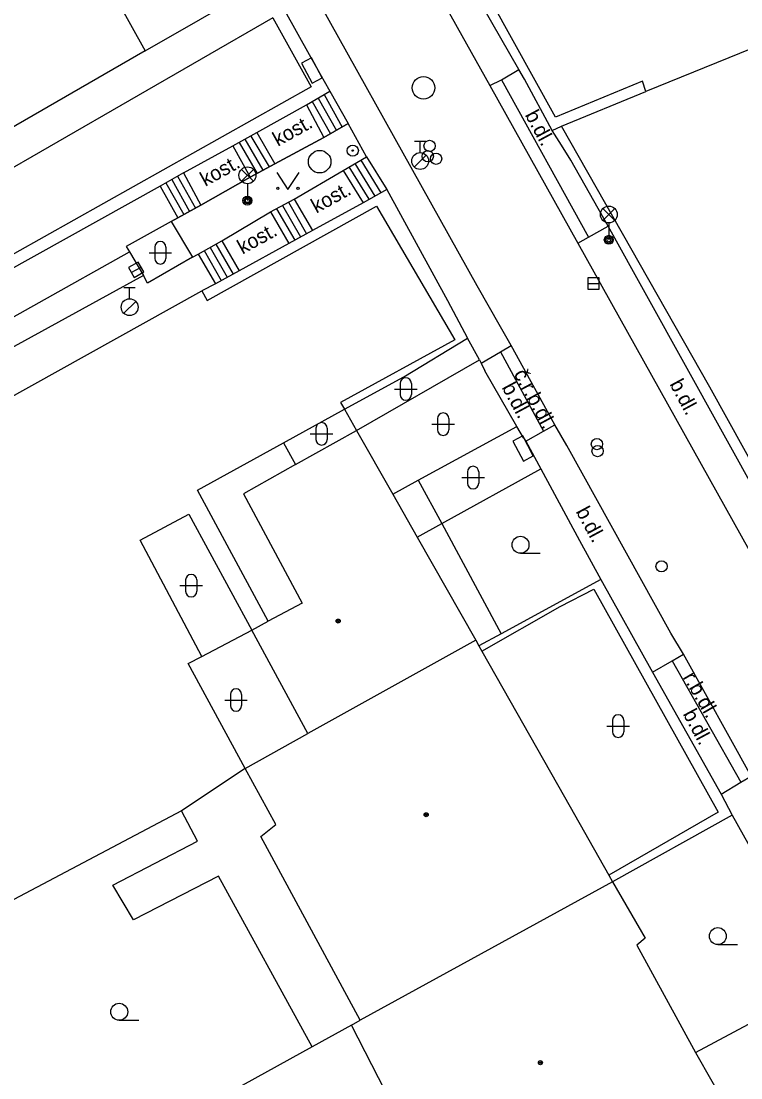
# Model space of a CAD drawing. Extents: x -600391 to -599491, y -1160176 to -1159402.
# Drawn here: x -600336.91 to -600304.95, y -1159781.21 to -1159734.28 of the extents above; entities that cross this region are included whole.
import ezdxf

# ---------------------------------------------------------------- set-up
doc = ezdxf.new("R2010")
doc.units = 0
for name, color, linetype in [('Level 10', 7, 'Continuous'), ('Level 11', 7, 'Continuous'), ('Level 24', 7, 'Continuous'), ('Level 25', 7, 'Continuous'), ('Level 27', 7, 'Continuous'), ('Level 28', 7, 'Continuous'), ('Level 33', 7, 'Continuous'), ('Level 36', 7, 'Continuous'), ('Level 39', 7, 'Continuous'), ('Level 40', 7, 'Continuous'), ('Level 5', 7, 'Continuous'), ('Level 51', 7, 'Continuous'), ('Level 7', 7, 'Continuous'), ('Level 8', 7, 'Continuous'), ('Level 9', 7, 'Continuous')]:
    doc.layers.add(name, color=color, linetype=linetype)

msp = doc.modelspace()

# ---------------------------------------------------------------- linework, layer by layer
at = {"layer": 'Level 10'}
for points in [[(-600328.52, -1159714.89), (-600328.3, -1159715.33), (-600321.84, -1159726.86), (-600316.09, -1159737.14)], [(-600315.15, -1159748.68), (-600315.62, -1159747.86), (-600316.66, -1159746.03), (-600326.09, -1159729.11), (-600327.4, -1159726.83)], [(-600316.09, -1159737.14), (-600312.19, -1159744.14)], [(-600312.19, -1159744.14), (-600302.73, -1159761.08)], [(-600313.21, -1159752.2), (-600315.15, -1159748.68)], [(-600307.5, -1159762.39), (-600308.05, -1159761.45), (-600312.68, -1159753.12), (-600313.21, -1159752.2)], [(-600304.49, -1159767.81), (-600307.5, -1159762.39)]]:
    msp.add_lwpolyline(points, dxfattribs=at)
at = {"layer": 'Level 11'}
for points in [[(-600331.4, -1159735.6), (-600326.48, -1159732.77)], [(-600325.73, -1159734.13), (-600338.47, -1159741.47)], [(-600315.57, -1159736.88), (-600314.81, -1159736.42)], [(-600316.09, -1159737.14), (-600315.57, -1159736.88)], [(-600315.57, -1159736.88), (-600311.71, -1159743.87)], [(-600323.2, -1159737.39), (-600322.39, -1159738.83)], [(-600323.98, -1159737.85), (-600323.17, -1159739.28)], [(-600323.72, -1159737.7), (-600322.91, -1159739.13)], [(-600323.45, -1159737.54), (-600322.65, -1159738.98)], [(-600324.24, -1159738), (-600323.47, -1159739.45)], [(-600322.39, -1159738.83), (-600323.47, -1159739.45)], [(-600321.57, -1159740.3), (-600322.39, -1159738.83)], [(-600326.7, -1159739.38), (-600325.9, -1159740.75)], [(-600326.44, -1159739.23), (-600325.64, -1159740.61)], [(-600327.51, -1159739.82), (-600326.74, -1159741.21)], [(-600327.23, -1159739.67), (-600326.43, -1159741.04)], [(-600326.97, -1159739.52), (-600326.17, -1159740.9)], [(-600323.47, -1159739.45), (-600325.64, -1159740.61)], [(-600322.61, -1159740.91), (-600321.57, -1159740.3)], [(-600321.57, -1159740.3), (-600320.67, -1159741.76)], [(-600325.64, -1159740.61), (-600326.74, -1159741.21)], [(-600322.35, -1159740.75), (-600321.46, -1159742.19)], [(-600322.09, -1159740.6), (-600321.2, -1159742.05)], [(-600321.83, -1159740.45), (-600320.93, -1159741.9)], [(-600329.96, -1159741.16), (-600329.17, -1159742.58)], [(-600329.7, -1159741.02), (-600328.93, -1159742.45)], [(-600326.74, -1159741.21), (-600328.93, -1159742.45)], [(-600324.78, -1159742.18), (-600322.61, -1159740.91)], [(-600322.61, -1159740.91), (-600321.72, -1159742.34)], [(-600330.74, -1159741.6), (-600329.95, -1159743.02)], [(-600330.48, -1159741.46), (-600329.69, -1159742.87)], [(-600330.22, -1159741.31), (-600329.43, -1159742.73)], [(-600325.84, -1159742.75), (-600324.78, -1159742.18)], [(-600324.78, -1159742.18), (-600323.97, -1159743.57)], [(-600328.93, -1159742.45), (-600329.95, -1159743.02)], [(-600325.57, -1159742.61), (-600324.76, -1159744)], [(-600325.3, -1159742.47), (-600324.5, -1159743.86)], [(-600325.04, -1159742.32), (-600324.24, -1159743.72)], [(-600329.95, -1159743.02), (-600330.24, -1159743.18)], [(-600327.99, -1159744.04), (-600325.84, -1159742.75)], [(-600325.84, -1159742.75), (-600325.02, -1159744.15)], [(-600330.24, -1159743.18), (-600332.24, -1159744.29), (-600332.1, -1159744.52)], [(-600330.24, -1159743.18), (-600329.3, -1159744.76)], [(-600311.71, -1159743.87), (-600310.84, -1159743.39)], [(-600329.05, -1159744.62), (-600327.99, -1159744.04)], [(-600327.99, -1159744.04), (-600327.23, -1159745.36)], [(-600312.19, -1159744.14), (-600311.71, -1159743.87)], [(-600352.17, -1159755.78), (-600332.1, -1159744.52)], [(-600332.1, -1159744.52), (-600331.48, -1159745.58)], [(-600328.78, -1159744.47), (-600328.02, -1159745.8)], [(-600328.52, -1159744.33), (-600327.76, -1159745.65)], [(-600328.26, -1159744.19), (-600327.49, -1159745.51)], [(-600329.3, -1159744.76), (-600331.29, -1159745.91), (-600331.48, -1159745.58)], [(-600329.3, -1159744.76), (-600329.05, -1159744.62)], [(-600329.05, -1159744.62), (-600328.28, -1159745.94)], [(-600331.48, -1159745.58), (-600340.25, -1159750.38)], [(-600315.62, -1159748.97), (-600315.15, -1159748.68)], [(-600316.48, -1159749.46), (-600315.62, -1159748.97)], [(-600315.62, -1159748.97), (-600313.71, -1159752.48)], [(-600322.02, -1159752.45), (-600316.56, -1159749.32)], [(-600325.25, -1159753), (-600322.55, -1159751.51)], [(-600322.55, -1159751.51), (-600322.02, -1159752.45)], [(-600319.27, -1159754.67), (-600314.89, -1159752.28)], [(-600314.5, -1159752.93), (-600313.71, -1159752.48)], [(-600313.71, -1159752.48), (-600313.21, -1159752.2)], [(-600324.72, -1159753.97), (-600327.04, -1159755.27), (-600324.43, -1159760.13), (-600325.94, -1159760.93)], [(-600318.23, -1159756.59), (-600313.83, -1159754.16)], [(-600320.4, -1159755.29), (-600319.27, -1159754.67)], [(-600319.27, -1159754.67), (-600318.23, -1159756.59)], [(-600328.89, -1159762.5), (-600331.62, -1159757.33), (-600329.46, -1159756.17), (-600326.67, -1159761.32)], [(-600319.32, -1159757.19), (-600318.23, -1159756.59)], [(-600318.23, -1159756.59), (-600315.59, -1159761.48)], [(-600328.89, -1159762.5), (-600326.67, -1159761.32)], [(-600326.96, -1159767.46), (-600329.49, -1159762.81), (-600328.89, -1159762.5)], [(-600308.87, -1159763.19), (-600307.99, -1159762.68)], [(-600307.99, -1159762.68), (-600307.5, -1159762.39)], [(-600307.99, -1159762.68), (-600304.95, -1159768.08)], [(-600304.95, -1159768.08), (-600304.49, -1159767.81)], [(-600305.82, -1159768.6), (-600304.95, -1159768.08)], [(-600306.96, -1159780.08), (-600301.17, -1159776.98)]]:
    msp.add_lwpolyline(points, dxfattribs=at)
at = {"layer": 'Level 24'}
for points in [[(-600324.456, -1159736.147), (-600323.985, -1159737.029), (-600323.544, -1159736.793), (-600324.015, -1159735.911)], [(-600315.076, -1159752.936), (-600314.606, -1159753.819), (-600314.164, -1159753.584), (-600314.634, -1159752.701)]]:
    msp.add_lwpolyline(points, close=True, dxfattribs=at)
at = {"layer": 'Level 25'}
for radius in [0.25, 0.0303]:
    msp.add_circle((-600322.18, -1159740.03), radius, dxfattribs=at)
at = {"layer": 'Level 27'}
for p, q in [((-600332.018, -1159745.443), (-600331.582, -1159745.197)), ((-600311.74, -1159745.93), (-600311.24, -1159745.93))]:
    msp.add_line(p, q, dxfattribs=at)
for points in [[(-600331.895, -1159745.66), (-600331.46, -1159745.415), (-600331.705, -1159744.98), (-600332.14, -1159745.225)], [(-600311.74, -1159746.18), (-600311.24, -1159746.18), (-600311.24, -1159745.68), (-600311.74, -1159745.68)]]:
    msp.add_lwpolyline(points, close=True, dxfattribs=at)
for centre in [(-600319.04, -1159737.24), (-600323.65, -1159740.52)]:
    msp.add_circle(centre, 0.5, dxfattribs=at)
at = {"layer": 'Level 28'}
for p, q in [((-600319.44, -1159739.615), (-600318.94, -1159739.615)), ((-600319.19, -1159740.115), (-600319.19, -1159739.615)), ((-600319.448, -1159740.762), (-600318.918, -1159740.232)), ((-600332.34, -1159746.105), (-600331.84, -1159746.105)), ((-600332.09, -1159746.605), (-600332.09, -1159746.105)), ((-600332.348, -1159747.252), (-600331.818, -1159746.722))]:
    msp.add_line(p, q, dxfattribs=at)
for centre, radius in [((-600318.77, -1159739.82), 0.25), ((-600319.19, -1159740.49), 0.375), ((-600318.85, -1159740.28), 0.25), ((-600318.48, -1159740.39), 0.25), ((-600332.09, -1159746.98), 0.375), ((-600311.34, -1159753.06), 0.25), ((-600311.31, -1159753.37), 0.25), ((-600308.47, -1159758.49), 0.25)]:
    msp.add_circle(centre, radius, dxfattribs=at)
at = {"layer": 'Level 33'}
for p, q in [((-600327.125, -1159741.39), (-600326.595, -1159740.86)), ((-600327.125, -1159740.86), (-600326.595, -1159741.39)), ((-600326.86, -1159741.5), (-600326.86, -1159742.25)), ((-600311.075, -1159743.13), (-600310.545, -1159742.6)), ((-600311.075, -1159742.6), (-600310.545, -1159743.13)), ((-600310.81, -1159743.24), (-600310.81, -1159743.99))]:
    msp.add_line(p, q, dxfattribs=at)
for centre, radius in [((-600326.86, -1159741.125), 0.375), ((-600326.86, -1159742.25), 0.2), ((-600326.86, -1159742.25), 0.145), ((-600326.86, -1159742.25), 0.0876), ((-600310.81, -1159742.865), 0.375), ((-600310.81, -1159743.99), 0.2), ((-600310.81, -1159743.99), 0.145), ((-600310.81, -1159743.99), 0.0876)]:
    msp.add_circle(centre, radius, dxfattribs=at)
at = {"layer": 'Level 36'}
for p, q in [((-600330.976, -1159744.316), (-600330.976, -1159744.816)), ((-600330.476, -1159744.316), (-600330.476, -1159744.816)), ((-600331.226, -1159744.566), (-600330.226, -1159744.566)), ((-600320.326, -1159750.616), (-600319.326, -1159750.616)), ((-600320.076, -1159750.366), (-600320.076, -1159750.866)), ((-600319.576, -1159750.366), (-600319.576, -1159750.866)), ((-600318.416, -1159751.926), (-600318.416, -1159752.426)), ((-600317.916, -1159751.926), (-600317.916, -1159752.426)), ((-600323.816, -1159752.356), (-600323.816, -1159752.856)), ((-600323.316, -1159752.356), (-600323.316, -1159752.856)), ((-600318.666, -1159752.176), (-600317.666, -1159752.176)), ((-600324.066, -1159752.606), (-600323.066, -1159752.606)), ((-600317.086, -1159754.296), (-600317.086, -1159754.796)), ((-600316.586, -1159754.296), (-600316.586, -1159754.796)), ((-600317.336, -1159754.546), (-600316.336, -1159754.546)), ((-600314.73, -1159757.905), (-600313.855, -1159757.905)), ((-600329.606, -1159759.096), (-600329.606, -1159759.596)), ((-600329.106, -1159759.096), (-600329.106, -1159759.596)), ((-600329.856, -1159759.346), (-600328.856, -1159759.346)), ((-600327.616, -1159764.176), (-600327.616, -1159764.676)), ((-600327.116, -1159764.176), (-600327.116, -1159764.676)), ((-600327.866, -1159764.426), (-600326.866, -1159764.426)), ((-600310.896, -1159765.586), (-600309.896, -1159765.586)), ((-600310.646, -1159765.336), (-600310.646, -1159765.836)), ((-600310.146, -1159765.336), (-600310.146, -1159765.836)), ((-600305.97, -1159775.285), (-600305.095, -1159775.285)), ((-600332.55, -1159778.645), (-600331.675, -1159778.645))]:
    msp.add_line(p, q, dxfattribs=at)
msp.add_lwpolyline([(-600325.56, -1159741), (-600325.06, -1159741.75), (-600324.56, -1159741)], dxfattribs=at)
for centre, radius in [((-600325.51, -1159741.7), 0.05), ((-600324.611, -1159741.7), 0.05), ((-600314.73, -1159757.53), 0.375), ((-600305.97, -1159774.91), 0.375), ((-600332.55, -1159778.27), 0.375)]:
    msp.add_circle(centre, radius, dxfattribs=at)
for centre, start, end in [((-600330.726, -1159744.316), 0, 180), ((-600330.726, -1159744.816), 180, 0), ((-600319.826, -1159750.366), 0, 180), ((-600319.826, -1159750.866), 180, 0), ((-600318.166, -1159751.926), 0, 180), ((-600323.566, -1159752.356), 0, 180), ((-600318.166, -1159752.426), 180, 0), ((-600323.566, -1159752.856), 180, 0), ((-600316.836, -1159754.296), 0, 180), ((-600316.836, -1159754.796), 180, 0), ((-600329.356, -1159759.096), 0, 180), ((-600329.356, -1159759.596), 180, 0), ((-600327.366, -1159764.176), 0, 180), ((-600327.366, -1159764.676), 180, 0), ((-600310.396, -1159765.336), 0, 180), ((-600310.396, -1159765.836), 180, 0)]:
    msp.add_arc(centre, 0.25, start, end, dxfattribs=at)
at = {"layer": 'Level 39'}
for centre, radius in [((-600322.83, -1159760.92), 0.09), ((-600322.83, -1159760.92), 0.0398), ((-600318.92, -1159769.52), 0.09), ((-600318.92, -1159769.52), 0.0398), ((-600313.85, -1159780.53), 0.09), ((-600313.85, -1159780.53), 0.0398)]:
    msp.add_circle(centre, radius, dxfattribs=at)
at = {"layer": 'Level 5'}
for points in [[(-600336.24, -1159726.9), (-600331.4, -1159735.6)], [(-600331.4, -1159735.6), (-600339.26, -1159740.12)], [(-600324.72, -1159753.97), (-600322.02, -1159752.45)], [(-600322.02, -1159752.45), (-600320.4, -1159755.29)], [(-600329.08, -1159755.1), (-600325.25, -1159753)], [(-600325.25, -1159753), (-600324.72, -1159753.97)], [(-600325.94, -1159760.93), (-600329.08, -1159755.1)], [(-600320.4, -1159755.29), (-600319.32, -1159757.19)], [(-600319.32, -1159757.19), (-600316.72, -1159761.77)], [(-600326.67, -1159761.32), (-600325.94, -1159760.93)], [(-600324.18, -1159765.92), (-600326.67, -1159761.32)], [(-600316.72, -1159761.77), (-600324.18, -1159765.92)], [(-600316.72, -1159761.77), (-600316.58, -1159762.02)], [(-600316.58, -1159762.02), (-600316.45, -1159762.26)], [(-600316.45, -1159762.26), (-600312.78, -1159768.72)], [(-600326.96, -1159767.46), (-600324.18, -1159765.92)], [(-600325.6, -1159769.96), (-600326.96, -1159767.46)], [(-600312.78, -1159768.72), (-600310.81, -1159772.2)], [(-600326.26, -1159770.49), (-600325.6, -1159769.96)], [(-600321.85, -1159778.65), (-600326.26, -1159770.49)], [(-600310.81, -1159772.2), (-600310.64, -1159772.5)], [(-600310.64, -1159772.5), (-600321.85, -1159778.65)], [(-600310.64, -1159772.5), (-600309.2, -1159775)], [(-600309.2, -1159775), (-600309.56, -1159775.31)], [(-600309.56, -1159775.31), (-600306.96, -1159780.08)], [(-600322.24, -1159778.87), (-600321.85, -1159778.65)], [(-600320.14, -1159782.97), (-600322.24, -1159778.87)], [(-600306.96, -1159780.08), (-600305.51, -1159782.63)]]:
    msp.add_lwpolyline(points, dxfattribs=at)
at = {"layer": 'Level 51'}
for points in [[(-600326.96, -1159767.46), (-600329.78, -1159769.35)], [(-600329.78, -1159769.35), (-600341.11, -1159775.33)], [(-600329.08, -1159770.69), (-600329.78, -1159769.35)], [(-600332.83, -1159772.65), (-600329.08, -1159770.69)], [(-600331.92, -1159774.18), (-600332.83, -1159772.65)], [(-600328.15, -1159772.25), (-600331.92, -1159774.18)], [(-600323.99, -1159779.83), (-600328.15, -1159772.25)], [(-600322.24, -1159778.87), (-600323.99, -1159779.83)], [(-600323.99, -1159779.83), (-600335.29, -1159786.07)]]:
    msp.add_lwpolyline(points, dxfattribs=at)
at = {"layer": 'Level 7'}
for points in [[(-600285.09, -1159727.62), (-600309.17, -1159737.41)], [(-600309.31, -1159736.95), (-600313.18, -1159738.55), (-600316.94, -1159731.75), (-600313.05, -1159729.5)], [(-600314.81, -1159736.42), (-600317.61, -1159731.54)], [(-600325.73, -1159734.13), (-600324.03, -1159737.2), (-600353.03, -1159753.48), (-600355.24, -1159749.56), (-600360.24, -1159740.73)], [(-600325.2, -1159733.82), (-600324.12, -1159735.76), (-600323.45, -1159736.94), (-600323.2, -1159737.39)], [(-600313.32, -1159739.14), (-600314.55, -1159736.85), (-600314.81, -1159736.42)], [(-600309.17, -1159737.41), (-600309.31, -1159736.95)], [(-600324.24, -1159738), (-600323.2, -1159737.39)], [(-600312.91, -1159738.94), (-600309.17, -1159737.41)], [(-600326.44, -1159739.23), (-600324.24, -1159738)], [(-600327.51, -1159739.82), (-600326.44, -1159739.23)], [(-600313.32, -1159739.14), (-600312.91, -1159738.94)], [(-600310.84, -1159743.39), (-600312.5, -1159740.46), (-600312.91, -1159739.78), (-600313.32, -1159739.14)], [(-600295.86, -1159757.73), (-600296.01, -1159757.35), (-600300.97, -1159760.2), (-600306.33, -1159750.54), (-600312.91, -1159738.94)], [(-600329.7, -1159741.02), (-600327.51, -1159739.82)], [(-600329.7, -1159741.02), (-600330.74, -1159741.6)], [(-600330.74, -1159741.6), (-600353.06, -1159754.02)], [(-600320.67, -1159741.76), (-600321.72, -1159742.34)], [(-600320.67, -1159741.76), (-600317.97, -1159746.68), (-600317.09, -1159748.35)], [(-600328.64, -1159746.68), (-600321.12, -1159742.5), (-600317.65, -1159748.43), (-600322.72, -1159751.21)], [(-600321.72, -1159742.34), (-600323.97, -1159743.57)], [(-600323.97, -1159743.57), (-600325.02, -1159744.15)], [(-600301.34, -1159760.31), (-600303.58, -1159756.43), (-600304.05, -1159755.63), (-600310.84, -1159743.39)], [(-600325.02, -1159744.15), (-600327.23, -1159745.36)], [(-600327.23, -1159745.36), (-600328.28, -1159745.94)], [(-600328.28, -1159745.94), (-600328.89, -1159746.26)], [(-600350.38, -1159758.22), (-600328.89, -1159746.26)], [(-600328.89, -1159746.26), (-600328.64, -1159746.68)], [(-600322.55, -1159751.51), (-600319.92, -1159750.07), (-600317.09, -1159748.35)], [(-600316.56, -1159749.32), (-600316.48, -1159749.46)], [(-600316.48, -1159749.46), (-600316.32, -1159749.81)], [(-600322.72, -1159751.21), (-600322.55, -1159751.51)], [(-600314.6, -1159752.79), (-600314.5, -1159752.93)], [(-600314.5, -1159752.93), (-600313.83, -1159754.16)], [(-600313.83, -1159754.16), (-600312.11, -1159757.34), (-600311.17, -1159759.07)], [(-600311.17, -1159759.07), (-600315.59, -1159761.48)], [(-600311.17, -1159759.07), (-600308.87, -1159763.19)], [(-600316.45, -1159762.26), (-600312.97, -1159760.28), (-600311.48, -1159759.51), (-600305.96, -1159769.41), (-600310.81, -1159772.2)], [(-600315.59, -1159761.48), (-600316.58, -1159762.02)], [(-600308.87, -1159763.19), (-600305.82, -1159768.6)], [(-600305.82, -1159768.6), (-600305.33, -1159769.54)], [(-600305.33, -1159769.54), (-600310.64, -1159772.5)], [(-600305.33, -1159769.54), (-600301.42, -1159776.53)]]:
    msp.add_lwpolyline(points, dxfattribs=at)
at = {"layer": 'Level 8'}
for points in [[(-600316.56, -1159749.32), (-600317.09, -1159748.35)], [(-600314.6, -1159752.79), (-600314.89, -1159752.28), (-600316.32, -1159749.81)]]:
    msp.add_lwpolyline(points, dxfattribs=at)
at = {"layer": 'Level 9'}
for points in [[(-600323.47, -1159739.45), (-600322.39, -1159738.83)], [(-600321.57, -1159740.3), (-600322.39, -1159738.83)], [(-600325.64, -1159740.61), (-600323.47, -1159739.45)], [(-600322.61, -1159740.91), (-600321.57, -1159740.3)], [(-600326.74, -1159741.21), (-600325.64, -1159740.61)], [(-600328.93, -1159742.45), (-600326.74, -1159741.21)], [(-600324.78, -1159742.18), (-600322.61, -1159740.91)], [(-600325.84, -1159742.75), (-600324.78, -1159742.18)], [(-600329.95, -1159743.02), (-600328.93, -1159742.45)], [(-600330.24, -1159743.18), (-600329.95, -1159743.02)], [(-600327.99, -1159744.04), (-600325.84, -1159742.75)], [(-600329.05, -1159744.62), (-600327.99, -1159744.04)], [(-600329.3, -1159744.76), (-600329.05, -1159744.62)]]:
    msp.add_lwpolyline(points, dxfattribs=at)

# ---------------------------------------------------------------- texts
at = {"layer": 'Level 40'}
for s, rotation, p in [('b.dl.', 298.28, (-600314.55, -1159738.44)), ('kost. ', 29, (-600325.51, -1159739.86)), ('kost. ', 29, (-600328.73, -1159741.64)), ('kost. ', 29, (-600323.8, -1159742.83)), ('kost. ', 29, (-600327.08, -1159744.65)), ('č.r.b.dl.', 298.28, (-600315.05, -1159749.94)), ('b.dl.', 298.28, (-600308.13, -1159750.39)), ('b.dl.', 298.28, (-600315.58, -1159750.54)), ('b.dl.', 298.28, (-600312.29, -1159756.05)), ('r.b.dl.', 300.1, (-600307.54, -1159763.41)), ('b.dl.', 298.28, (-600307.54, -1159765.04))]:
    msp.add_text(s, height=0.65, rotation=rotation, dxfattribs=at).set_placement(p)

doc.saveas('drawing.dxf')
